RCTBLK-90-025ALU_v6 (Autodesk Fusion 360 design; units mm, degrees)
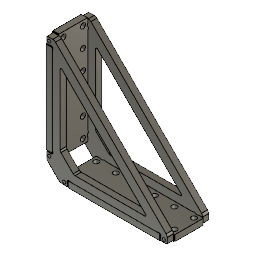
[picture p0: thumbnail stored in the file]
parameter "t_sheet_MAIN" = 6.35 (= "1 / 4 * 1") comment "thickness of the sheet"
parameter "hw_m6_drill" = 5 comment "5mm for zund bit"
parameter "r_cutoutTool" = 2.05 (= "4.1 mm / 2")
parameter "hw_m3_thru" = 3.25
parameter "hw_m3_head" = 5.5
parameter "hw_m3_washer" = 7
parameter "hw_m3_thread" = 2.5
parameter "tab_breather" = 0.2 comment "offset for tabs"
parameter "hw_m5_thread" = 4.2
parameter "hw_m5_head" = 8.5
parameter "hw_m5_washer" = 10
parameter "hw_m5_thru" = 5.25
parameter "hw_m6_thru" = 6.5
parameter "hw_m6_head" = 10
parameter "hw_m6_washer" = 12
parameter "hw_plstf6_thread" = 2.94
parameter "hw_plstf6_thru" = 4
parameter "hw_plstf6_head" = 6.86
parameter "hw_plstf6_washer" = 7.92
parameter "hw_m3_flathead" = 6
parameter "d99" = 20
parameter "d124" = 9.525 (= "t_sheet_MAIN * 1.5")
parameter "d129" = 3
parameter "d213" = 0.2 (= "tab_breather")
parameter "d732" = 0.5
parameter "d893" = 2.25
parameter "d939" = 7.5 (= "hw_m3_head + 2 mm")
parameter "d940" = 5.75 (= "d939 / 2 + 2 mm")
parameter "d1335" = 2
sketch "Sketch56" plane through (0, 0, 0) normal (0, 1, 0) x axis (1, 0, 0)
  dimension "d1309" = 6.35 (= "t_sheet_MAIN")
  dimension "d1318" = 20
  dimension "d1319" = 8.5 (= "hw_m5_head")
  dimension "d1320" = 6
  dimension "d1322" = 6 (= "d1320")
  dimension "d1324" = 20
  dimension "d1328" = 5
  dimension "d1329" = 5
  dimension "d1332" = 0.5
  dimension "d1333" = 0.5
  dimension "d1334" = 45
  dimension "d1336" = 1
  dimension "d1337" = 2 (= "d1335")
  dimension "d1338" = 2 (= "d1335")
  dimension "d1339" = 1
  dimension "d1340" = 7 (= "d1343")
  dimension "d1341" = 7 (= "d1340")
  dimension "d1342" = 1
  dimension "d1343" = 7
  dimension "d1344" = 0.2 (= "tab_breather")
  dimension "d1345" = 0.2 (= "d1344")
  dimension "d1346" = 0.2 (= "tab_breather")
  dimension "d1347" = 0.2 (= "tab_breather")
  dimension "d1348" = 7 (= "d1343")
  dimension "d1361" = 3.5 (= "d1340 / 2")
  dimension "d1362" = 3.25 (= "hw_m3_thru")
  dimension "d1363" = 3.5 (= "d1341 / 2")
  dimension "d1387" = 125 (= "( ( ( num_mounts_f1 - 1 ) * 20 ) * 1 mm ) + 25 * 1 mm")
  dimension "d1388" = 125 (= "( ( num_mounts_f2 - 1 ) * 20 ) * 1 mm + 25 mm")
  dimension "d1398" = 10
  dimension "d1399" = 8
  dimension "d1400" = 8 (= "d1399")
  dimension "d1401" = 20
extrude "Extrude159" new body sketch "Sketch56" along normal blind 6.35 (= "t_sheet_MAIN")
extrude "Extrude160" new body sketch "Sketch56" against normal blind 15 (magnitude of "( ( -( num_mounts_deep - 1 ) * 20 - 10 ) / 2 ) * 1 mm")
extrude "Extrude161" new body sketch "Sketch56" along normal blind 6.35 (= "t_sheet_MAIN")
combine "Combine30"
combine "Combine31"
sketch "Sketch57" plane through (0, 6.35, 0) normal (0, 1, 0) x axis (-1, 0, 0)
  dimension "d1356" = 45
  dimension "d1357" = 45
  dimension "d1358" = 4.1 (= "r_cutoutTool * 2")
extrude "Extrude162" cut sketch "Sketch57" no distance stored
sketch "Sketch58" plane through (0, 0, 0) normal (-1, 0, 0) x axis (0, -1, 0)
  dimension "d1365" = 4.1 (= "r_cutoutTool * 2")
  dimension "d1366" = 3.25 (= "hw_m3_thru")
  dimension "d1367" = 4.5
  dimension "d1368" = 4.5 (= "d1367")
  dimension "d1377" = 20
  dimension "d1378" = 5.25 (= "hw_m5_thru")
  dimension "d1379" = 5
  dimension "d1380" = 8.5
  dimension "d1411" = 45
  dimension "d1414" = 45
extrude "Extrude163" cut sketch "Sketch58" no distance stored
sketch "Sketch59" plane through (0, 0, 0) normal (0, 0, -1) x axis (1, 0, 0)
  dimension "d1371" = 4.1 (= "r_cutoutTool * 2")
  dimension "d1373" = 3.25 (= "hw_m3_thru")
  dimension "d1374" = 4.5
  dimension "d1412" = 45
  dimension "d1413" = 45
extrude "Extrude164" cut sketch "Sketch59" no distance stored
extrude "Extrude165" cut sketch "Sketch58" no distance stored
rectangular_pattern "R-Pattern10" countU 6 (= "num_mounts_f1") uSpaceDistance 20 vSpaceDistance 20
sketch "Sketch60" plane through (0, 0, 0) normal (0, 0, -1) x axis (1, 0, 0)
  dimension "d1389" = 5
  dimension "d1390" = 5
  dimension "d1391" = 5.25 (= "hw_m5_thru")
extrude "Extrude166" cut sketch "Sketch60" no distance stored
rectangular_pattern "R-Pattern11" countU 6 (= "num_mounts_f2") uSpaceDistance -20 vSpaceDistance 20
extrude "Extrude167" cut sketch "Sketch56" along normal blind 6.35 (= "t_sheet_MAIN")
fillet "Fillet79" ChordLen 2
fillet "Fillet80" ChordLen 0.5
fillet "Fillet81" ChordLen 0.5
fillet "Fillet82" radius 0.5
fillet "Fillet83" ChordLen 3
mirror "Mirror31"
combine "Combine32"
combine "Combine33"
named bodies: "Body192 (1)", "Body192 (2)", "Body192 (3)", "Body192 (4)", "Body192 (5)", "Body192 (6)", "Body192 (7)", "Body192 (8)", "Body192 (9)", "Body192 (10)", "Body192 (11)", "Body192 (12)", "Body192 (13)", "Body192 (14)", "Body192 (15)", "Body192 (16)", "Rail (2) (1)", "Rail (2) (2)", "Rail (2) (2) (1)"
